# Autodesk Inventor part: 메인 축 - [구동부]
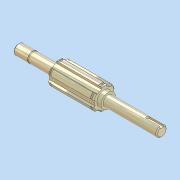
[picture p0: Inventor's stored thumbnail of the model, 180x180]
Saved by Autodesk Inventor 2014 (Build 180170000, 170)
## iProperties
Created: 2012-05
Part Number: 메인 축 - [구동부]
Document SubType Name: 모델링
Designer: SeoGD™
Mass: 21.4462 g
Surface Area: 72.5109 cm^2
Volume: 21.4462 cm^3
Density: 1 g/cm^3
Material: 강철, 연강
Appearance: 강철
변환 표준: STEP AP214IS
파일 이름: C:\Users\SeoGD\Desktop\?쒗뿕\硫붿씤 異?.stp
전처리기: Build: 253, Release: 2010 SP1 - Date: Wed 07/29/2009
전송 단위: 밀리미터
불확실성: 0.01
Author: SeoGD™
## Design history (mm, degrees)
sketch "스케치1"
  geometry: L1 (-69.5, 0)-(69.5, 0); L2 (69.5, 0)-(69.5, 5); L3 (69.5, 5)-(55.5, 5); L4 (55.5, 5)-(55.5, 4.8); L5 (55.5, 4.8)-(54.35, 4.8); L6 (54.35, 4.8)-(54.35, 5); L7 (54.35, 5)-(30.5, 5); L8 (30.5, 5)-(30.5, 9); L9 (30.5, 9)-(-13.5, 9); L10 (-13.5, 9)-(-13.5, 7); L11 (-13.5, 7)-(-17.5, 7); L12 (-17.5, 7)-(-17.5, 5); L13 (-17.5, 5)-(-69.5, 5); L14 (-69.5, 5)-(-69.5, 0); 2 further points
  constraints: 28 end point, 9 parallel, 4 collinear, 2 perpendicular, 1 coincident, 1 horizontal, 1 midpoint
  dimensions: "d2" = 1.15 distance between parallel lines of L6 L4; "d3" = 10 diameter of L3 L1; "d4" = 9.6 diameter of L5 L1; "d6" = 44 distance between parallel lines of L10 L8; "d7" = 4 distance between parallel lines of L12 L10; "d8" = 14 diameter of L11 L1; "d9" = 18 diameter of L9 L1; "d33" = 52 distance from line of L12.end L14; "d37" = 39 distance between parallel lines of L8 L2; "d38" = 14 distance between parallel lines of L2 L4
revolve "회전1" sketch "스케치1" stored, may be unused: angle "d10" = 90 deg
sketch "스케치2"
  geometry: L1 (2.5, 10.712)-(2.5, 8.646); L2 (-2.5, 10.712)-(-2.5, 8.646); A1 r 9 centre (0, 0) between (2.5, 8.646) and (-2.5, 8.646) reference; A2 r 11 centre (0, 0) between (2.5, 10.712) and (-2.5, 10.712); 1 further point
  constraints: 4 end point, 4 point on circle, 2 parallel, 1 centre point, 1 coincident, 1 vertical
  dimensions: "d11" = 22 diameter of A2; "d12" = 5 distance between parallel lines of L1 L2
extrude "돌출1" join sketch "스케치2" stored distance "d13" = 10; taper "d14" = 0 deg
chamfer "모따기1" distance "d15" = 1; stored, may be unused: second distance "d16" = 2, angle "d17" = 45 deg
node "작업 평면1"
node "작업 평면2"
sketch "스케치3"
  geometry: L1 (2.5, 10.712)-(2.5, 10.198); L2 (-2.5, 10.712)-(-2.5, 10.198); A1 r 11 centre (0, 0) between (2.5, 10.712) and (-2.5, 10.712) reference; A2 r 10.5 centre (0, 0) between (2.5, 10.198) and (-2.5, 10.198); 1 further point
  constraints: 4 end point, 2 point on circle, 1 centre point, 1 coincident, 1 parallel, 1 vertical
  dimensions: "d19" = 21 diameter of A2
extrude "돌출2" cut sketch "스케치3" distance "d20" = 1.35; taper "d21" = 0 deg
node "작업 평면3"
sketch "스케치4"
  geometry: L1 (-26, -5)-(-26, 5) reference; L2 (-26, 1.5)-(-12.5, 1.5); L3 (-12.5, -1.5)-(-26, -1.5); A1 r 1.5 centre (-12.5, 0) between (-12.5, -1.5) and (-12.5, 1.5); 2 further points
  constraints: 4 end point, 2 perpendicular, 2 point on circle, 2 point on line, 2 tangent, 1 centre point, 1 horizontal alignment, 1 midpoint
  dimensions: "d25" = 3 distance between parallel lines of L3 L2; "d26" = 15 dimension on A1 L1
extrude "돌출3" cut sketch "스케치4" distance "d27" = 1.8; taper "d28" = 0 deg
chamfer "모따기2" distance "d29" = 1; stored, may be unused: second distance "d30" = 2, angle "d31" = 45 deg
node "솔리드1"
node "솔리드 본체"
node "곡면 본체"
mirror "대칭1"
pattern_circular "원형 패턴1" dims "d23" = 360 deg
node "솔리드2"
other parameters: "d18" = -1.65
